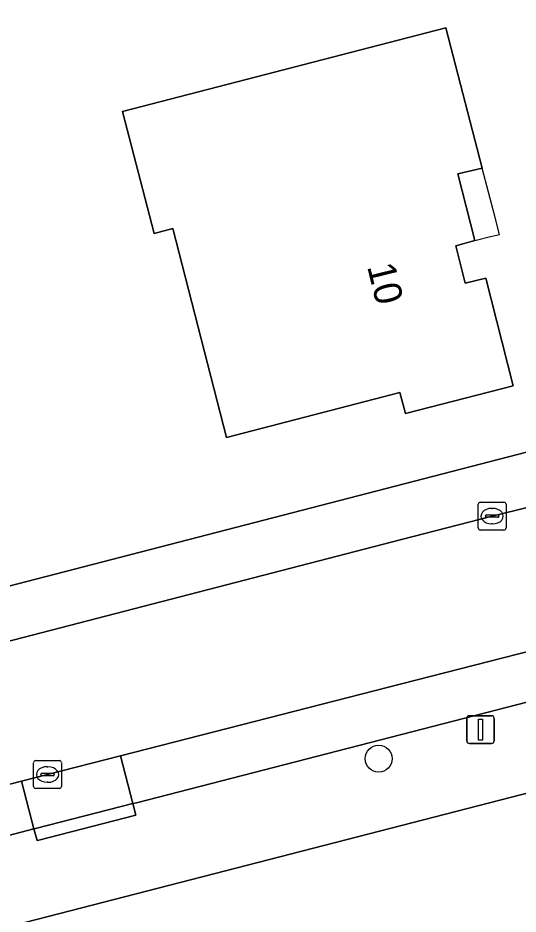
# Model space of a CAD drawing. Extents: x 158835 to 160077, y 386387 to 387778.
# Drawn here: x 159486.21 to 159504.19, y 386718.95 to 386751.2 of the extents above; entities that cross this region are included whole.
import ezdxf

# ---------------------------------------------------------------- set-up
doc = ezdxf.new("R2010")
doc.units = 0
for name, color, linetype in [('IMGEO_Boom', 7, 'Continuous'), ('IMGEO_Erf', 7, 'Continuous'), ('IMGEO_Kolk', 7, 'Continuous'), ('IMGEO_Lichtmast', 7, 'Continuous'), ('IMGEO_Muur', 7, 'Continuous'), ('IMGEO_Pand', 7, 'Continuous'), ('IMGEO_Pand_nummerreeks', 7, 'Continuous'), ('IMGEO_Pand_overbouw', 7, 'Continuous'), ('IMGEO_Parkeervlak_open', 7, 'Continuous'), ('IMGEO_Rijbaan_lokaal_open', 7, 'Continuous'), ('IMGEO_Voetpad_open', 7, 'Continuous')]:
    doc.layers.add(name, color=color, linetype=linetype)

msp = doc.modelspace()

# ---------------------------------------------------------------- linework, layer by layer
at = {"layer": 'IMGEO_Boom'}
msp.add_circle((159499.181, 386724.544), 0.489, dxfattribs=at)
at = {"layer": 'IMGEO_Erf'}
for points in [[(159464.145, 386725.103), (159472.554, 386727.311), (159478.638, 386728.88), (159494.722, 386733.042), (159509.916, 386736.979), (159508.841, 386742.529), (159507.134, 386750), (159505.112, 386757.158), (159504.369, 386759.274)], [(159511.887, 386716.039), (159511.952, 386719.617), (159511.746, 386722.739), (159511.714, 386722.925), (159511.666, 386723.107), (159511.601, 386723.285), (159511.521, 386723.456), (159511.426, 386723.619), (159511.317, 386723.773), (159511.195, 386723.916), (159511.06, 386724.048), (159510.914, 386724.168), (159510.758, 386724.274), (159510.593, 386724.365), (159510.42, 386724.442), (159510.242, 386724.502), (159510.058, 386724.547), (159509.872, 386724.575), (159509.683, 386724.586), (159509.495, 386724.581), (159509.443, 386724.576), (159500, 386722.142), (159452.288, 386709.846)]]:
    msp.add_lwpolyline(points, dxfattribs=at)
msp.add_lwpolyline([(159501.593, 386750.839), (159502.9, 386745.791), (159502.028, 386745.583), (159502.639, 386743.186), (159501.957, 386743.001), (159502.286, 386741.659), (159503.037, 386741.833), (159504.019, 386737.957), (159500.145, 386736.962), (159499.938, 386737.72), (159493.708, 386736.103), (159491.783, 386743.626), (159491.11, 386743.445), (159489.972, 386747.836)], close=True, dxfattribs=at)
at = {"layer": 'IMGEO_Kolk'}
for p, q in [((159502.76, 386732.845), (159502.76, 386733.697)), ((159502.835, 386733.771), (159503.687, 386733.771)), ((159503.248, 386733.551), (159503.273, 386733.551)), ((159503.761, 386733.697), (159503.761, 386732.845)), ((159503.019, 386733.265), (159503.019, 386733.277)), ((159503.457, 386733.228), (159503.059, 386733.228)), ((159503.062, 386733.314), (159503.46, 386733.314)), ((159503.503, 386733.277), (159503.503, 386733.265)), ((159503.271, 386732.991), (159503.246, 386732.991)), ((159503.687, 386732.771), (159502.835, 386732.771)), ((159486.849, 386724.474), (159487.701, 386724.474)), ((159486.774, 386723.548), (159486.774, 386724.4)), ((159487.262, 386724.254), (159487.287, 386724.254)), ((159487.775, 386724.4), (159487.775, 386723.548)), ((159487.033, 386723.968), (159487.033, 386723.98)), ((159487.471, 386723.931), (159487.073, 386723.931)), ((159487.076, 386724.017), (159487.474, 386724.017)), ((159487.517, 386723.98), (159487.517, 386723.968)), ((159487.285, 386723.694), (159487.26, 386723.694)), ((159487.701, 386723.474), (159486.849, 386723.474))]:
    msp.add_line(p, q, dxfattribs=at)
for points in [[(159502.76, 386732.845), (159502.76, 386733.697)], [(159502.835, 386733.771), (159503.687, 386733.771)], [(159503.761, 386733.697), (159503.761, 386732.845)], [(159503.687, 386732.771), (159502.835, 386732.771)], [(159486.849, 386724.474), (159487.701, 386724.474)], [(159486.774, 386723.548), (159486.774, 386724.4)], [(159487.775, 386724.4), (159487.775, 386723.548)], [(159487.701, 386723.474), (159486.849, 386723.474)]]:
    msp.add_lwpolyline(points, dxfattribs=at)
for centre, radius, start, end in [((159502.837, 386733.695), 0.0765, 91.552, 178.448), ((159502.837, 386733.695), 0.0765, 91.552, 178.448), ((159503.685, 386733.695), 0.0765, 1.552, 88.448), ((159503.685, 386733.695), 0.0765, 1.552, 88.448), ((159503.059, 386733.274), 0.0403, 85.8775, 175.7526), ((159503.056, 386733.264), 0.0366, 178.938, 274.7102), ((159503.46, 386733.271), 0.043, 264.8664, 352.4533), ((159503.464, 386733.276), 0.0386, 1.7309, 96.639), ((159502.837, 386732.847), 0.0765, 181.552, 268.448), ((159502.837, 386732.847), 0.0765, 181.552, 268.448), ((159503.685, 386732.847), 0.0765, 271.552, 358.448), ((159503.685, 386732.847), 0.0765, 271.552, 358.448), ((159486.851, 386724.398), 0.0765, 91.552, 178.448), ((159486.851, 386724.398), 0.0765, 91.552, 178.448), ((159487.699, 386724.398), 0.0765, 1.552, 88.448), ((159487.699, 386724.398), 0.0765, 1.552, 88.448), ((159487.073, 386723.977), 0.0403, 85.8775, 175.7526), ((159487.07, 386723.967), 0.0366, 178.938, 274.7102), ((159487.474, 386723.974), 0.043, 264.8664, 352.4533), ((159487.478, 386723.979), 0.0386, 1.7309, 96.639), ((159486.851, 386723.55), 0.0765, 181.552, 268.448), ((159486.851, 386723.55), 0.0765, 181.552, 268.448), ((159487.699, 386723.55), 0.0765, 271.552, 358.448), ((159487.699, 386723.55), 0.0765, 271.552, 358.448)]:
    msp.add_arc(centre, radius, start, end, dxfattribs=at)
for centre, major_axis, ratio, start_param, end_param in [((159503.247, 386733.271), (-0.387, 0.002), 0.722429, 4.712389, 7.853982), ((159503.272, 386733.271), (-0.39, 0.002), 0.717154, 1.570796, 4.712389), ((159487.261, 386723.974), (-0.387, 0.002), 0.722429, 4.712389, 7.853982), ((159487.286, 386723.974), (-0.39, 0.002), 0.717154, 1.570796, 4.712389)]:
    msp.add_ellipse(centre, major_axis=major_axis, ratio=ratio, start_param=start_param, end_param=end_param, dxfattribs=at)
at = {"layer": 'IMGEO_Lichtmast'}
for p, q in [((159502.446, 386726.088), (159503.236, 386726.088)), ((159503.236, 386726.088), (159502.446, 386726.088)), ((159502.346, 386725.188), (159502.346, 386725.988)), ((159502.346, 386725.988), (159502.346, 386725.188)), ((159503.336, 386725.988), (159503.336, 386725.188)), ((159503.336, 386725.188), (159503.336, 386725.988)), ((159503.236, 386725.088), (159502.446, 386725.088)), ((159502.446, 386725.088), (159503.236, 386725.088))]:
    msp.add_line(p, q, dxfattribs=at)
msp.add_lwpolyline([(159502.766, 386725.963), (159502.916, 386725.963), (159502.916, 386725.213), (159502.766, 386725.213), (159502.766, 386725.963)], dxfattribs=at)
for centre, start, end in [((159502.446, 386725.988), 90, 180), ((159502.446, 386725.988), 90, 180), ((159503.236, 386725.988), 0, 90), ((159503.236, 386725.988), 360, 90), ((159502.446, 386725.188), 180, 270), ((159502.446, 386725.188), 180, 270), ((159503.236, 386725.188), 270, 0), ((159503.236, 386725.188), 270, 0)]:
    msp.add_arc(centre, 0.1, start, end, dxfattribs=at)
at = {"layer": 'IMGEO_Muur'}
msp.add_lwpolyline([(159494.722, 386733.042), (159478.638, 386728.88)], dxfattribs=at)
at = {"layer": 'IMGEO_Pand'}
msp.add_lwpolyline([(159502.9, 386745.791), (159501.593, 386750.839), (159489.972, 386747.836), (159491.11, 386743.445), (159491.783, 386743.626), (159493.708, 386736.103), (159499.938, 386737.72), (159500.145, 386736.962), (159504.019, 386737.957), (159503.037, 386741.833), (159502.286, 386741.659), (159501.957, 386743.001), (159502.639, 386743.186), (159502.028, 386745.583)], close=True, dxfattribs=at)
at = {"layer": 'IMGEO_Pand_overbouw'}
msp.add_lwpolyline([(159502.639, 386743.186), (159503.206, 386743.328), (159503.524, 386743.408), (159503.36, 386744.067), (159502.9, 386745.791), (159502.028, 386745.583)], close=True, dxfattribs=at)
at = {"layer": 'IMGEO_Parkeervlak_open'}
msp.add_lwpolyline([(159505.257, 386728.584), (159500, 386727.237), (159489.901, 386724.649), (159490.342, 386722.927), (159490.47, 386722.96), (159500, 386725.418), (159507.582, 386727.373)], dxfattribs=at)
msp.add_lwpolyline([(159486.339, 386723.736), (159482.497, 386722.75), (159482.942, 386721.017), (159486.786, 386722.02)], close=True, dxfattribs=at)
at = {"layer": 'IMGEO_Rijbaan_lokaal_open'}
msp.add_lwpolyline([(159500, 386727.237), (159505.257, 386728.584), (159509.764, 386729.781), (159510.326, 386729.92), (159509.609, 386734.841), (159503.261, 386733.27), (159500, 386732.427), (159484.395, 386728.392), (159477.382, 386726.586), (159473.743, 386725.638), (159466.706, 386723.831), (159450.742, 386719.718), (159449.649, 386719.445), (159448.769, 386719.226), (159450.032, 386714.409), (159459.295, 386716.79), (159462.852, 386717.704), (159469.368, 386719.379), (159478.768, 386721.793), (159482.497, 386722.75), (159486.339, 386723.736), (159487.275, 386723.976), (159489.901, 386724.649)], close=True, dxfattribs=at)
at = {"layer": 'IMGEO_Voetpad_open'}
for points in [[(159466.706, 386723.831), (159473.743, 386725.638), (159473.631, 386726.051), (159477.258, 386727.008), (159477.382, 386726.586), (159484.395, 386728.392), (159500, 386732.427), (159503.261, 386733.27), (159509.609, 386734.841), (159510.219, 386734.992), (159509.916, 386736.979), (159494.722, 386733.042), (159478.638, 386728.88), (159472.554, 386727.311), (159464.145, 386725.103)], [(159507.582, 386727.373), (159500, 386725.418), (159490.47, 386722.96), (159490.342, 386722.927), (159490.449, 386722.511), (159486.963, 386721.611), (159486.897, 386721.595), (159486.786, 386722.02), (159482.942, 386721.017)], [(159452.288, 386709.846), (159500, 386722.142), (159509.443, 386724.576)]]:
    msp.add_lwpolyline(points, dxfattribs=at)
for points in [[(159489.901, 386724.649), (159487.275, 386723.976), (159486.339, 386723.736), (159486.786, 386722.02), (159486.837, 386722.033), (159490.342, 386722.927)], [(159490.449, 386722.511), (159490.342, 386722.927), (159486.837, 386722.033), (159486.786, 386722.02), (159486.897, 386721.595), (159486.963, 386721.611)]]:
    msp.add_lwpolyline(points, close=True, dxfattribs=at)

# ---------------------------------------------------------------- texts
at = {"layer": 'IMGEO_Pand_nummerreeks'}
msp.add_text('10', height=1, rotation=283.7748, dxfattribs=at).set_placement((159498.762, 386742.257))

doc.saveas('drawing.dxf')
